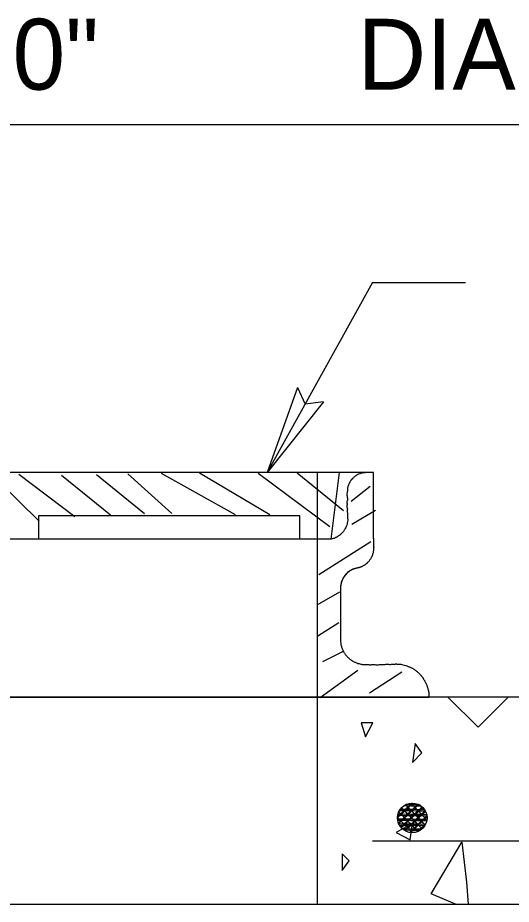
# Model space of a CAD drawing. Extents: x 26.41 to 33.74, y 20.66 to 30.6.
# Drawn here: x 32.251 to 32.669, y 27.658 to 28.409 of the extents above; entities that cross this region are included whole.
import ezdxf

# ---------------------------------------------------------------- set-up
doc = ezdxf.new("R2010")
doc.units = 0
for name, color, linetype in [('DETL-DIMS', 7, 'Continuous'), ('DETL-LINE', 7, 'Continuous'), ('DETL-NOTE', 7, 'Continuous'), ('DETL-PATT', 7, 'Continuous')]:
    doc.layers.add(name, color=color, linetype=linetype)

msp = doc.modelspace()

# ---------------------------------------------------------------- linework, layer by layer
at = {"layer": 'DETL-DIMS'}
for p, q in [((31.7863, 28.31876), (33.34406, 28.31876)), ((32.55162, 28.185), (32.46248, 28.02397)), ((32.55162, 28.185), (32.63023, 28.185)), ((32.48803, 28.09609), (32.46248, 28.02397)), ((32.48803, 28.09609), (32.49447, 28.08175)), ((32.51004, 28.08391), (32.46248, 28.02397)), ((32.51004, 28.08391), (32.49447, 28.08175))]:
    msp.add_line(p, q, dxfattribs=at)
at = {"layer": 'DETL-LINE'}
for p, q in [((32.55233, 28.02397), (31.9326, 28.02397)), ((32.50501, 27.65839), (32.50501, 28.02397)), ((32.51648, 27.96753), (32.5236, 28.02397)), ((32.55233, 27.968), (32.55233, 28.02397)), ((32.26909, 27.98718), (32.26909, 27.96753)), ((32.49015, 27.98718), (32.26909, 27.98718)), ((32.49015, 27.96753), (32.49015, 27.98718)), ((32.51641, 27.96753), (31.96848, 27.96753)), ((32.5245, 27.92622), (32.5245, 27.88094)), ((33.34406, 27.83377), (31.7863, 27.83377)), ((31.88579, 27.83377), (32.59918, 27.83377)), ((32.35804, 27.83377), (32.32774, 27.83377)), ((32.58425, 27.74341), (32.57473, 27.73425)), ((32.58472, 27.74313), (32.57517, 27.73397)), ((32.58712, 27.74046), (32.5776, 27.73126)), ((32.58759, 27.74014), (32.57804, 27.73098)), ((32.58032, 27.74183), (32.58947, 27.73232)), ((32.59297, 27.74038), (32.58346, 27.73114)), ((32.5934, 27.74006), (32.58385, 27.73087)), ((32.58613, 27.74171), (32.59533, 27.7322)), ((32.57438, 27.73613), (32.58354, 27.72658)), ((32.58417, 27.73759), (32.57462, 27.72839)), ((32.5846, 27.73727), (32.57509, 27.72812)), ((32.58892, 27.73322), (32.57568, 27.73346)), ((32.58896, 27.7344), (32.57572, 27.73464)), ((32.589, 27.73735), (32.57576, 27.73759)), ((32.58904, 27.73853), (32.5758, 27.73877)), ((32.57725, 27.73315), (32.58641, 27.72359)), ((32.57733, 27.73896), (32.58653, 27.72945)), ((32.58704, 27.73464), (32.57749, 27.72544)), ((32.58747, 27.73433), (32.57796, 27.72513)), ((32.59305, 27.73315), (32.57981, 27.73338)), ((32.59309, 27.73433), (32.57984, 27.73456)), ((32.59313, 27.73727), (32.57988, 27.73751)), ((32.59317, 27.73845), (32.57992, 27.73869)), ((32.5802, 27.73602), (32.5894, 27.72646)), ((32.58999, 27.73751), (32.58047, 27.72827)), ((32.59046, 27.73719), (32.58087, 27.728)), ((32.58303, 27.73307), (32.59227, 27.72348)), ((32.58315, 27.73885), (32.59234, 27.72933)), ((32.59285, 27.73452), (32.58334, 27.72532)), ((32.59329, 27.73421), (32.58374, 27.72501)), ((32.59718, 27.73307), (32.58393, 27.7333)), ((32.59722, 27.73425), (32.58397, 27.73448)), ((32.58602, 27.73594), (32.59521, 27.72635)), ((32.59584, 27.73739), (32.58629, 27.72819)), ((32.59623, 27.73708), (32.58672, 27.72788)), ((32.57426, 27.73028), (32.58342, 27.72076)), ((32.58877, 27.72497), (32.57552, 27.72521)), ((32.58881, 27.72615), (32.57556, 27.72639)), ((32.58885, 27.7291), (32.5756, 27.72933)), ((32.58888, 27.73028), (32.57564, 27.73051)), ((32.59289, 27.72489), (32.57965, 27.72513)), ((32.59293, 27.72607), (32.57969, 27.72631)), ((32.59297, 27.72902), (32.57973, 27.72925)), ((32.59301, 27.7302), (32.57977, 27.73043)), ((32.58008, 27.7302), (32.58928, 27.72065)), ((32.58991, 27.73165), (32.58036, 27.72249)), ((32.59034, 27.73134), (32.58079, 27.72214)), ((32.59278, 27.72867), (32.58322, 27.71951)), ((32.59317, 27.72839), (32.58366, 27.71919)), ((32.5971, 27.72894), (32.58385, 27.72918)), ((32.59714, 27.73012), (32.58389, 27.73036)), ((32.59572, 27.73153), (32.58617, 27.72238)), ((32.59616, 27.73122), (32.58661, 27.72206)), ((32.59285, 27.72194), (32.57961, 27.72218)), ((33.29328, 27.71188), (32.55162, 27.71188)), ((31.86633, 27.65839), (33.24596, 27.65839))]:
    msp.add_line(p, q, dxfattribs=at)
for points in [[(32.58173, 27.74026), (32.57265, 27.73153)], [(32.5813, 27.74058), (32.57269, 27.73224)], [(32.57615, 27.74018), (32.58366, 27.73244)], [(32.58488, 27.74399), (32.57772, 27.73712)], [(32.58908, 27.74148), (32.57788, 27.74168)], [(32.58495, 27.74156), (32.57788, 27.74168)], [(32.58083, 27.74164), (32.57788, 27.74168)], [(32.58558, 27.74399), (32.57815, 27.7368)], [(32.57949, 27.7427), (32.58664, 27.73531)], [(32.58908, 27.74262), (32.57977, 27.74282)], [(32.58499, 27.7427), (32.57977, 27.74282)], [(32.58087, 27.74278), (32.57977, 27.74282)], [(32.59274, 27.7414), (32.57996, 27.74164)], [(32.59089, 27.74262), (32.58, 27.74282)], [(32.58983, 27.74309), (32.58059, 27.73413)], [(32.58488, 27.74399), (32.58071, 27.73999)], [(32.59038, 27.74285), (32.58098, 27.73385)], [(32.58558, 27.74399), (32.5811, 27.73967)], [(32.58983, 27.74309), (32.58358, 27.737)], [(32.59038, 27.74285), (32.58397, 27.73668)], [(32.58401, 27.74396), (32.58959, 27.73814)], [(32.58401, 27.74396), (32.59246, 27.73519)], [(32.59274, 27.7414), (32.58409, 27.74156)], [(32.59089, 27.74262), (32.58413, 27.74274)], [(32.59344, 27.74081), (32.58641, 27.73401)], [(32.59384, 27.7405), (32.58684, 27.73374)], [(32.59274, 27.7414), (32.58822, 27.74148)], [(32.59089, 27.74262), (32.58826, 27.74266)], [(32.5912, 27.74246), (32.59258, 27.74101)], [(32.5912, 27.74246), (32.59545, 27.73806)], [(32.5912, 27.74246), (32.59627, 27.73719)], [(32.59199, 27.74164), (32.59627, 27.73719)], [(32.57874, 27.73739), (32.57265, 27.73153)], [(32.5758, 27.73452), (32.57265, 27.73153)], [(32.57265, 27.73193), (32.57768, 27.7267)], [(32.57265, 27.73193), (32.58055, 27.72371)], [(32.57831, 27.73771), (32.57269, 27.73224)], [(32.57536, 27.73484), (32.57269, 27.73224)], [(32.5848, 27.7333), (32.57285, 27.7335)], [(32.58067, 27.73338), (32.57285, 27.7335)], [(32.57654, 27.73346), (32.57285, 27.7335)], [(32.58484, 27.73448), (32.57308, 27.73468)], [(32.58071, 27.73452), (32.57308, 27.73468)], [(32.57658, 27.7346), (32.57308, 27.73468)], [(32.58118, 27.73472), (32.5734, 27.72725)], [(32.57819, 27.73189), (32.5734, 27.72725)], [(32.58161, 27.7344), (32.57363, 27.72674)], [(32.57379, 27.73672), (32.58067, 27.72957)], [(32.58488, 27.73743), (32.57426, 27.73763)], [(32.58075, 27.73751), (32.57426, 27.73763)], [(32.57662, 27.73759), (32.57426, 27.73763)], [(32.58491, 27.73857), (32.57497, 27.73877)], [(32.58079, 27.73865), (32.57497, 27.73877)], [(32.57666, 27.73873), (32.57497, 27.73877)], [(32.59623, 27.73719), (32.58401, 27.73743)], [(32.59553, 27.73837), (32.58405, 27.73861)], [(32.59749, 27.73307), (32.58806, 27.73322)], [(32.5973, 27.73425), (32.5881, 27.7344)], [(32.59623, 27.73719), (32.58814, 27.73735)], [(32.59553, 27.73837), (32.58818, 27.73853)], [(32.58888, 27.73295), (32.59604, 27.72552)], [(32.589, 27.73877), (32.59745, 27.72996)], [(32.59745, 27.73319), (32.58916, 27.72525)], [(32.59604, 27.73755), (32.58928, 27.73106)], [(32.59753, 27.73256), (32.58959, 27.72493)], [(32.59627, 27.73712), (32.58971, 27.73075)], [(32.59187, 27.73582), (32.59745, 27.72996)], [(32.59745, 27.73319), (32.59215, 27.72808)], [(32.59753, 27.73256), (32.59258, 27.7278)], [(32.59474, 27.73283), (32.59745, 27.72996)], [(32.59482, 27.73865), (32.59627, 27.73719)], [(32.57281, 27.73165), (32.57265, 27.73153)], [(32.58476, 27.73036), (32.57269, 27.73055)], [(32.58063, 27.73043), (32.57269, 27.73055)], [(32.5765, 27.73047), (32.57269, 27.73055)], [(32.58472, 27.72918), (32.57285, 27.72937)], [(32.58059, 27.72925), (32.57285, 27.72937)], [(32.57646, 27.72933), (32.57285, 27.72937)], [(32.57525, 27.72902), (32.5734, 27.72725)], [(32.57867, 27.73153), (32.57363, 27.72674)], [(32.57568, 27.7287), (32.57363, 27.72674)], [(32.58468, 27.72623), (32.57375, 27.72642)], [(32.58055, 27.72631), (32.57375, 27.72642)], [(32.57642, 27.72635), (32.57375, 27.72642)], [(32.58464, 27.72505), (32.57438, 27.72525)], [(32.58051, 27.72513), (32.57438, 27.72525)], [(32.57639, 27.72521), (32.57438, 27.72525)], [(32.58405, 27.73177), (32.57552, 27.72356)], [(32.58106, 27.7289), (32.57552, 27.72356)], [(32.57812, 27.72603), (32.57552, 27.72356)], [(32.58448, 27.73146), (32.57587, 27.72316)], [(32.5815, 27.72863), (32.57587, 27.72316)], [(32.57855, 27.72576), (32.57587, 27.72316)], [(32.57713, 27.72733), (32.58503, 27.71907)], [(32.58692, 27.72878), (32.5787, 27.72084)], [(32.58393, 27.72591), (32.5787, 27.72084)], [(32.58735, 27.72851), (32.57918, 27.72061)], [(32.58436, 27.72564), (32.57918, 27.72061)], [(32.58295, 27.72721), (32.58987, 27.72002)], [(32.58979, 27.7258), (32.58295, 27.71927)], [(32.59022, 27.72552), (32.58366, 27.71919)], [(32.59561, 27.72485), (32.58378, 27.72505)], [(32.59627, 27.72599), (32.58381, 27.72623)], [(32.5859, 27.73008), (32.59344, 27.72226)], [(32.59561, 27.72485), (32.5879, 27.72497)], [(32.59627, 27.72599), (32.58794, 27.72615)], [(32.5973, 27.72894), (32.58798, 27.7291)], [(32.59749, 27.73012), (32.58802, 27.73028)], [(32.58877, 27.72709), (32.59344, 27.72226)], [(32.59659, 27.72666), (32.58955, 27.7199)], [(32.59565, 27.72572), (32.58955, 27.7199)], [(32.59592, 27.72529), (32.59097, 27.72053)], [(32.59592, 27.72529), (32.59097, 27.72053)], [(32.59175, 27.72996), (32.59604, 27.72552)], [(32.59659, 27.72666), (32.59203, 27.72226)], [(32.59592, 27.72529), (32.59246, 27.72194)], [(32.59462, 27.72698), (32.59604, 27.72552)], [(32.59659, 27.72666), (32.59502, 27.72513)], [(32.59592, 27.72529), (32.59545, 27.72481)], [(32.58873, 27.72202), (32.57682, 27.72222)], [(32.5846, 27.7221), (32.57682, 27.72222)], [(32.58047, 27.72218), (32.57682, 27.72222)], [(32.58869, 27.72084), (32.57843, 27.72104)], [(32.58456, 27.72092), (32.57843, 27.72104)], [(32.58043, 27.721), (32.57843, 27.72104)], [(32.58095, 27.72304), (32.5787, 27.72084)], [(32.58142, 27.72277), (32.57918, 27.72061)], [(32.5914, 27.7208), (32.57957, 27.721)], [(32.58, 27.72434), (32.58503, 27.71907)], [(32.58283, 27.72135), (32.58503, 27.71907)], [(32.5868, 27.72293), (32.58295, 27.71927)], [(32.58381, 27.7201), (32.58295, 27.71927)], [(32.58723, 27.72265), (32.58366, 27.71919)], [(32.58429, 27.71978), (32.58366, 27.71919)], [(32.5914, 27.7208), (32.5837, 27.72092)], [(32.59305, 27.72194), (32.58374, 27.7221)], [(32.58582, 27.72422), (32.58987, 27.72002)], [(32.5914, 27.7208), (32.58782, 27.72084)], [(32.59305, 27.72194), (32.58786, 27.72202)], [(32.58869, 27.72124), (32.58987, 27.72002)], [(32.59266, 27.72285), (32.58955, 27.7199)], [(32.58967, 27.71998), (32.58955, 27.7199)], [(32.59305, 27.72253), (32.59097, 27.72053)], [(32.59164, 27.72411), (32.59344, 27.72226)]]:
    msp.add_lwpolyline(points, dxfattribs=at)
msp.add_circle((32.58512, 27.73153), 0.01249, dxfattribs=at)
msp.add_arc((32.54157, 27.92627), 0.01708, 100.53205, 180.19488, dxfattribs=at)
for points in [[(32.55233, 28.02397), (32.54526, 28.02381), (32.5418, 28.02334), (32.5396, 28.02251), (32.53861, 28.022), (32.53736, 28.02126), (32.53622, 28.02039), (32.53535, 28.01961), (32.53476, 28.01909), (32.53449, 28.0189), (32.53417, 28.01843), (32.5337, 28.01795), (32.53339, 28.0174), (32.53291, 28.01685), (32.53244, 28.01611), (32.53197, 28.01516), (32.53166, 28.01465), (32.53122, 28.01351), (32.53071, 28.0121), (32.53048, 28.01096), (32.53032, 28.00958), (32.53024, 28.00832), (32.52993, 28.00707), (32.52985, 28.00483), (32.53016, 28.00322), (32.53004, 27.9998), (32.52969, 27.99885), (32.52993, 27.99752), (32.52989, 27.99469), (32.53016, 27.99374), (32.53012, 27.99056), (32.5304, 27.98958), (32.53024, 27.98576), (32.53059, 27.98451), (32.53048, 27.98258), (32.53016, 27.98132), (32.53, 27.98046), (32.52934, 27.9783), (32.52839, 27.97657), (32.52792, 27.9755), (32.52721, 27.97472), (32.52647, 27.97362), (32.5258, 27.97287), (32.52521, 27.97228), (32.52474, 27.97193), (32.52434, 27.97146), (32.52376, 27.97091), (32.5225, 27.97012), (32.52136, 27.96937), (32.52077, 27.96906), (32.5203, 27.96886), (32.51955, 27.96847), (32.51833, 27.968), (32.51641, 27.96753)], [(32.55233, 27.968), (32.55229, 27.96666), (32.55241, 27.96556), (32.55229, 27.96481), (32.55241, 27.96379), (32.55245, 27.96257), (32.55245, 27.96171), (32.55245, 27.95994), (32.55233, 27.95923), (32.55229, 27.95817), (32.55217, 27.95719), (32.55194, 27.95585), (32.55162, 27.95479), (32.55139, 27.95404), (32.55123, 27.95357), (32.55092, 27.95294), (32.55048, 27.95192), (32.54974, 27.9507), (32.54899, 27.94968), (32.5484, 27.94878), (32.54757, 27.94799), (32.54702, 27.9474), (32.54667, 27.94709), (32.54526, 27.94591), (32.54408, 27.94524), (32.54298, 27.94461), (32.54243, 27.94426), (32.5414, 27.9439), (32.54077, 27.94367), (32.53983, 27.94339), (32.53869, 27.94316), (32.53736, 27.94284), (32.53563, 27.94233), (32.53496, 27.94206), (32.53441, 27.94182), (32.53382, 27.94154), (32.53335, 27.94127), (32.53283, 27.94099), (32.53205, 27.94048), (32.53138, 27.94001), (32.53087, 27.93954), (32.53, 27.93891), (32.52942, 27.93828), (32.52898, 27.93789), (32.528, 27.93667), (32.52714, 27.93545), (32.52666, 27.93463), (32.52627, 27.93392), (32.52588, 27.9329), (32.52545, 27.93211), (32.52521, 27.93144), (32.52501, 27.9307), (32.5249, 27.92999), (32.52462, 27.92889), (32.52454, 27.92794), (32.5245, 27.92688), (32.5245, 27.92622)], [(32.5245, 27.88094), (32.52482, 27.87814), (32.52521, 27.87677), (32.5256, 27.87547), (32.52615, 27.87421), (32.52666, 27.87307), (32.5271, 27.87221), (32.52761, 27.87142), (32.52808, 27.87056), (32.52875, 27.86969), (32.52934, 27.86899), (32.53, 27.8682), (32.53079, 27.86737), (32.53134, 27.8669), (32.53185, 27.86643), (32.53244, 27.866), (32.53311, 27.86541), (32.5337, 27.86506), (32.53441, 27.86458), (32.53496, 27.86427), (32.53594, 27.86372), (32.53688, 27.86329), (32.53818, 27.86274), (32.54015, 27.86215), (32.54156, 27.86183), (32.54266, 27.86156), (32.5484, 27.8614), (32.5495, 27.8612), (32.55056, 27.86136), (32.55441, 27.8612), (32.55536, 27.86116), (32.55665, 27.86116), (32.55791, 27.86144), (32.56172, 27.86136), (32.56271, 27.8616), (32.56585, 27.86156), (32.56679, 27.86148), (32.56809, 27.86183), (32.57065, 27.86168), (32.57128, 27.86203), (32.57214, 27.86183), (32.57367, 27.86175), (32.57462, 27.86168), (32.57627, 27.86144), (32.57855, 27.86097), (32.58067, 27.86026), (32.58291, 27.85936), (32.58393, 27.85896), (32.58476, 27.85849), (32.58531, 27.85822), (32.58605, 27.85771), (32.58696, 27.85716), (32.58763, 27.85672), (32.58849, 27.85602), (32.5892, 27.85539), (32.59014, 27.8546), (32.59077, 27.85397), (32.59179, 27.85287), (32.59242, 27.85224), (32.59262, 27.85201), (32.59293, 27.85157), (32.59333, 27.85114), (32.59368, 27.85075), (32.59407, 27.85028), (32.59439, 27.84957), (32.59466, 27.84894), (32.59521, 27.84827), (32.59565, 27.8476), (32.59612, 27.8467), (32.59659, 27.84568), (32.59757, 27.84344), (32.5984, 27.84065), (32.5991, 27.83778), (32.59918, 27.83377)]]:
    msp.add_spline(points, degree=3, dxfattribs=at)
at = {"layer": 'DETL-PATT'}
for p, q in [((32.26961, 27.98266), (32.23038, 28.02126)), ((32.2996, 27.98659), (32.25235, 28.0222)), ((32.32982, 27.98796), (32.28851, 28.02153)), ((32.35875, 27.98903), (32.31807, 28.02196)), ((32.38167, 27.98938), (32.34448, 28.02279)), ((32.43563, 27.98804), (32.3731, 28.02326)), ((32.46456, 27.98824), (32.40517, 28.02338)), ((32.51542, 27.9779), (32.45473, 28.02314)), ((32.5269, 27.99154), (32.48779, 28.0235)), ((32.53354, 27.99964), (32.54946, 28.01257)), ((32.55398, 27.99182), (32.53394, 27.97999)), ((32.50603, 27.93754), (32.55005, 27.96556)), ((32.52344, 27.92272), (32.50434, 27.91155)), ((32.50524, 27.88581), (32.52301, 27.89705)), ((32.52678, 27.87248), (32.50906, 27.8638)), ((32.50729, 27.83361), (32.53905, 27.85657)), ((32.54899, 27.83754), (32.57619, 27.85523))]:
    msp.add_line(p, q, dxfattribs=at)
for points in [[(32.66636, 27.83377), (32.64085, 27.80826), (32.61534, 27.83377)], [(32.62167, 27.65839), (32.60123, 27.66723), (32.62717, 27.7111), (32.63094, 27.67714), (32.63244, 27.65839)]]:
    msp.add_lwpolyline(points, dxfattribs=at)
for points in [[(32.5418, 27.81203), (32.54557, 27.80024), (32.5517, 27.81203)], [(32.58755, 27.79458), (32.58519, 27.77854), (32.59321, 27.78656)], [(32.57151, 27.71911), (32.5833, 27.71298), (32.58519, 27.72713)], [(32.52576, 27.70119), (32.52576, 27.68704), (32.53189, 27.69506)]]:
    msp.add_lwpolyline(points, close=True, dxfattribs=at)

# ---------------------------------------------------------------- texts
at = {"layer": 'DETL-NOTE'}
for s, p in [('6\'-0"', (32.16037, 28.34824)), ('DIAM.', (32.53893, 28.34824))]:
    msp.add_text(s, height=0.05998, dxfattribs=at).set_placement(p)

doc.saveas('drawing.dxf')
